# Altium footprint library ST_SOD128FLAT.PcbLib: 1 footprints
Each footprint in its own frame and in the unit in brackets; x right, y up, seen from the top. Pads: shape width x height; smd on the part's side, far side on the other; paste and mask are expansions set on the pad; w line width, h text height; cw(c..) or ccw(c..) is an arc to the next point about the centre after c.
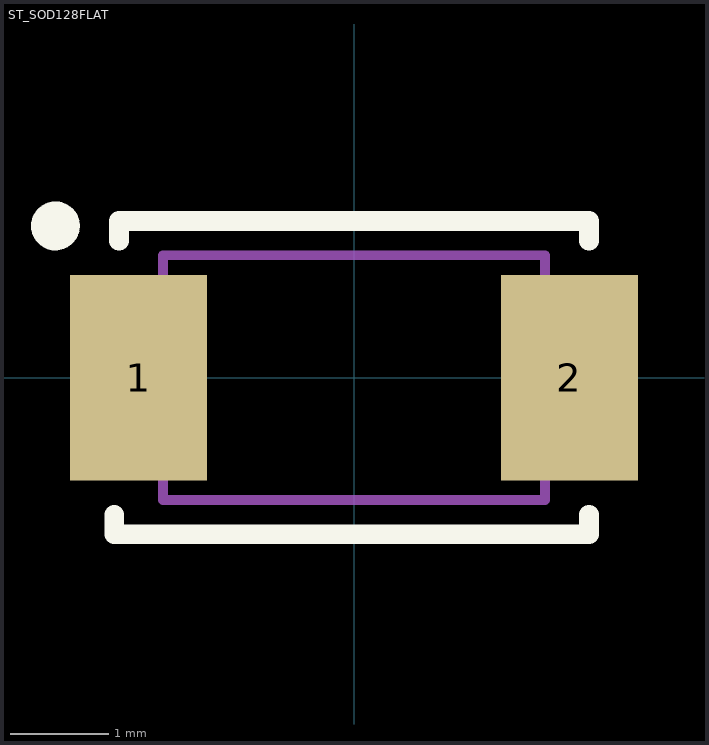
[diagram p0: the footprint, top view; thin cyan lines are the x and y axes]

## ST_SOD128FLAT [mm]
height 1.03
pads (2):
  rect 1.4x2.1 smd paste-20: 1(-2.2,0) 2(2.2,0)
Top Overlay:
  circle w0.25: c-3.05,1.55 r0.125
  lines w0.2: -2.45,-1.4 -2.45,-1.6 2.4,-1.6 2.4,-1.4 ; -2.4,1.4 -2.4,1.6 2.4,1.6 2.4,1.4
Top Paste:
  rectangle: -2.865,-0.995 -1.535,0.995
  rectangle: 1.535,-0.995 2.865,0.995
Mechanical 13:
  lines w0.1: -1.95,-1.25 1.95,-1.25 1.95,1.25 -1.95,1.25 -1.95,-1.25
3D body: height 1.03, standoff 0, extent 0,0 0,0
3D body: height 1.1, standoff 0, extent -1.95,-1.25 1.95,1.25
